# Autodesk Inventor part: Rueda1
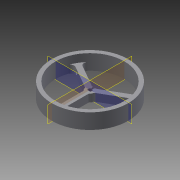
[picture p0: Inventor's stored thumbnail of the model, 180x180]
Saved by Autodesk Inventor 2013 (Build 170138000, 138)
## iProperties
Created: 2012-12
Part Number: Rueda1
Material: Generic
Document SubType Name: Modeling
Designer: ALUMNO
Density: 1 g/cm^3
Author: ALUMNO
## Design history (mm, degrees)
sketch "Sketch1"
  geometry: L1 (-27, 0)-(27, 0); L2 (-1.118, -1)-(1.118, -1); L3 (0, -3.5)-(0, -10.5); L4 (0, 42.566)-(0, -45.394) reference; L5 (2, -2.872)-(2, -26.926); L6 (-2, -2.872)-(-2, -26.926); L7 (3.031, 1.75)-(9.093, 5.25); L8 (-3.031, 1.75)-(-9.093, 5.25); L9 (3.487, -0.296)-(24.318, 11.731); L10 (1.487, 3.168)-(22.318, 15.195); L11 (-22.318, 15.195)-(-1.487, 3.168); L12 (-24.318, 11.731)-(-3.487, -0.296); L13 (0, 0)-(2.042, 7.62); L14 (0, 0)-(-1.877, 7.007); L15 (0.388, 1.449)-(0.906, 3.381); L16 (-0.388, 1.449)-(-0.906, 3.381); C1 r 30 at (0, 0); A1 r 27 centre (0, 0) between (2, -26.926) and (24.318, 11.731); A2 r 27 centre (0, 0) between (22.318, 15.195) and (-22.318, 15.195); A3 r 27 centre (0, 0) between (-24.318, 11.731) and (-2, -26.926); A4 r 3.5 centre (0, 0) between (-3.487, -0.296) and (-2, -2.872); A5 r 3.5 centre (0, 0) between (2, -2.872) and (3.487, -0.296); A6 r 3.5 centre (0, 0) between (1.487, 3.168) and (0.906, 3.381); A7 r 3.5 centre (0, 0) between (-0.906, 3.381) and (-1.487, 3.168); A8 r 1.5 centre (0, 0) between (1.118, -1) and (0.388, 1.449); A9 r 1.5 centre (0, 0) between (-0.388, 1.449) and (-1.118, -1); 1 further point
  constraints: 30 end point, 21 point on circle, 10 centre point, 7 parallel, 5 point on line, 4 coincident, 1 collinear, 1 horizontal, 1 midpoint, 1 perpendicular, 10 other
  dimensions: "d3" = 1 distance between parallel lines of L2 L1; "d4" = 2 distance between parallel lines of L5 L3; "d5" = 2 distance between parallel lines of L3 L6 (= d4); "d8" = 360 deg dimension on point (0, 0) L3.start (derived); "d10" = 2 distance between parallel lines of L10 L7 (derived); "d11" = 2 distance between parallel lines of L9 L7 (= d10); "d12" = 2 distance between parallel lines of L11 L8 (= d10); "d13" = 2 distance between parallel lines of L8 L12 (= d10); "d17" = 3.5 radius of A5; "d18" = 3.5 radius of A4 (= d17); "d19" = 15 deg angle of L4 L13; "d20" = 15 deg angle of L4 L14 (= d19); "d21" = 3.5 radius of A6 (= d17); "d22" = 3.5 radius of A7 (= d17); "d23" = 1.5 radius of A9; "d24" = 1.5 radius of A8 (= d23); "d25" = 60 diameter of C1; "d81" = 3 radial gap between concentric circles of C1 A2; "d84" = 3 radial gap between concentric circles of A1 C1 (derived); "d85" = 3 radial gap between concentric circles of C1 A3 (derived)
extrude "Extrusion1" new body sketch "Sketch1" distance "d26" = 6; taper "d27" = 0 deg
fillet "Fillet10" dims "d56" = 1
fillet "Fillet11" dims "d57" = 3
sketch "Sketch5"
  geometry: C1 r 30 at (0, 0) reference; C2 r 30 at (0, 0); C3 r 27 at (0, 0); A1 r 27 centre (0, 0) between (-25.682, 8.332) and (-5.625, -26.408) reference
  constraints: 2 centre point, 2 coincident, 2 concentric
extrude "Extrusion2" join sketch "Sketch5" distance "d86" = 6; taper "d87" = 0 deg
sketch "Sketch4" dims "d97" = 10
  geometry: L1 (0, 7.671)-(0, -6.568); L2 (30.159, 6.072)-(30.159, 0.082); C1 r 1.5 at (29.956, 3.286); C2 r 1.5 at (29.956, 8.786); 1 further point
  constraints: 4 end point, 2 centre point, 2 vertical, 1 parallel, 2 other
  dimensions: "d100" = 5.5 distance of C1.centre C2.centre
revolve "Revolution2" sketch "Sketch4" stored, may be unused: angle "d78" = 90 deg
body "Solid1"
other parameters: "d0" = 21, "d1" = 7, "d2" = 3, "d31" = 5, "d37" = 2, "d45" = 2.5, "d58" = 6, "d63" = 8, "d65" = 7, "d73" = 7
